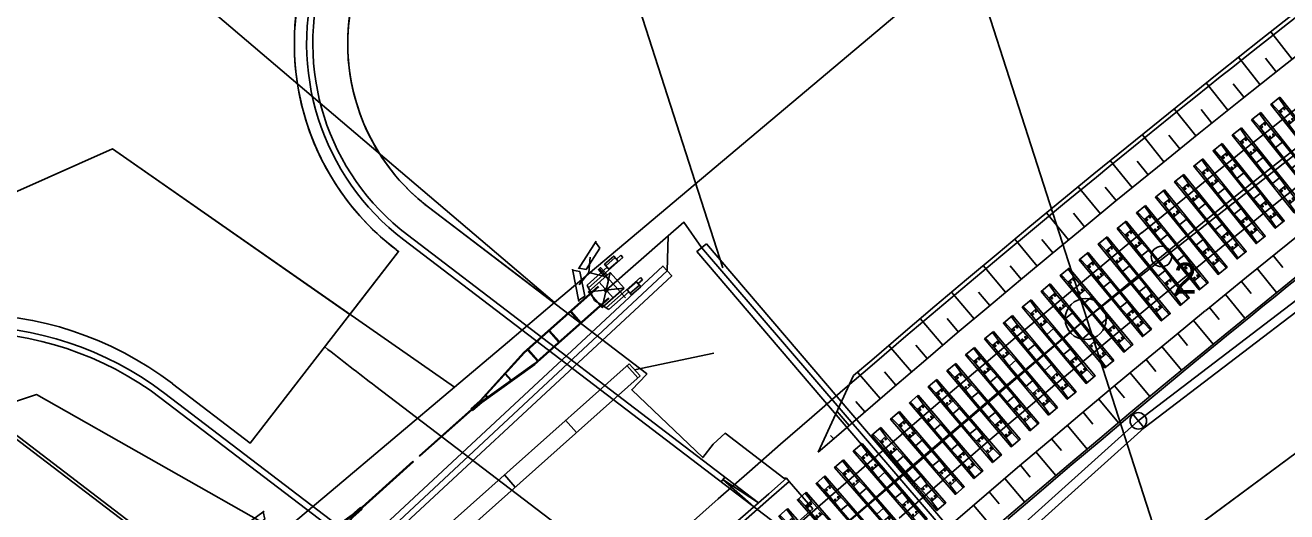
# Model space of a CAD drawing. Extents: x -758836 to -757729, y -1175316 to -1174366.
# Drawn here: x -758418.54 to -758387.81, y -1174837.29 to -1174825.45 of the extents above; entities that cross this region are included whole.
import ezdxf

# ---------------------------------------------------------------- set-up
doc = ezdxf.new("R2010")
doc.units = 0
for name, color, linetype in [('_NOR-návrh silná', 7, 'Continuous'), ('_NOR-návrh tenká', 7, 'Continuous'), ('_NOR-osa', 7, 'Continuous'), ('_NOR-pomocná', 7, 'Continuous'), ('_NOR-popis', 7, 'Continuous'), ('_NOR-pražce', 7, 'Continuous'), ('_NOR-přejezdová konstrukce', 7, 'Continuous'), ('_NOR-sanace', 7, 'Continuous'), ('_NOR-svahy', 7, 'Continuous'), ('_NOR-vytyčení', 7, 'Continuous'), ('G_Obvod stavby', 7, 'Continuous'), ('Hranice parcel', 7, 'Continuous'), ('KOS_kabely SSZT', 7, 'Continuous'), ('KOS_PZZ nové', 7, 'Continuous'), ('Vrstva 1', 7, 'Continuous')]:
    doc.layers.add(name, color=color, linetype=linetype)

# ---------------------------------------------------------------- blocks, each defined once
blk = doc.blocks.new('půdorys-SB8')
at = {"layer": '_NOR-pražce'}
for p, q in [((-1.21, 0.109), (-0.96, 0.095)), ((-0.96, 0.095), (-0.56, 0.099)), ((-0.96, 0.095), (-0.96, -0.095)), ((-0.56, 0.099), (-0.32, 0.109)), ((-0.56, 0.099), (-0.56, -0.1)), ((-0.32, 0.109), (0.32, 0.109)), ((-0.32, 0.109), (-0.32, -0.11)), ((0.56, 0.099), (0.32, 0.109)), ((0.32, -0.11), (0.32, 0.109)), ((0.96, 0.095), (0.56, 0.099)), ((0.56, 0.099), (0.56, -0.1)), ((1.21, 0.109), (0.96, 0.095)), ((0.96, 0.095), (0.96, -0.095)), ((-1.21, -0.11), (-0.96, -0.095)), ((-0.96, -0.095), (-0.56, -0.1)), ((-0.56, -0.1), (-0.32, -0.11)), ((-0.32, -0.11), (0.32, -0.11)), ((0.56, -0.1), (0.32, -0.11)), ((0.96, -0.095), (0.56, -0.1)), ((1.21, -0.11), (0.96, -0.095))]:
    blk.add_line(p, q, dxfattribs=at)
blk.add_lwpolyline([(-1.21, 0.142), (1.21, 0.142), (1.21, -0.142), (-1.21, -0.142)], close=True, dxfattribs=at)
for centre in [(-0.916, 0.048), (-0.604, 0.048), (0.604, 0.048), (0.916, 0.048), (-0.916, -0.048), (-0.604, -0.048), (0.604, -0.048), (0.916, -0.048)]:
    blk.add_circle(centre, 0.015, dxfattribs=at)
blk = doc.blocks.new('A$C45C32C5D')
for p, q in [((0.338, 0.725), (0, 0)), ((0.328, 0.702), (0.449, 0.568)), ((0.011, 0.023), (0.192, 0.016))]:
    blk.add_line(p, q)
blk.add_lwpolyline([(0.449, 0.568), (0.192, 0.016)])
blk = doc.blocks.new('A$C45E25FDC')
for p, q in [((0.029, 0.671), (0.224, 0.671)), ((0.341, 0.159), (0.341, 0.557)), ((0.341, 0.159), (0, 0))]:
    blk.add_line(p, q)
blk.add_arc((0.227, 0.557), 0.115, 0.0129, 91.4438)
blk = doc.blocks.new('Závora 8m')
for p, q in [((0.083, -0.373), (-0.058, -0.373)), ((-0.058, -0.448), (-0.058, -0.373)), ((1.054, -0.448), (-0.058, -0.448)), ((1.032, -0.373), (0.382, -0.373)), ((0.413, -1.026), (1.122, -0.517)), ((0.413, -0.517), (1.122, -1.026)), ((0.542, -0.323), (0.542, -1.27)), ((0.767, -0.517), (0.767, -1.026)), ((0.851, -0.571), (5.271, -0.571)), ((0.851, -0.591), (5.271, -0.591)), ((1.149, -0.771), (1.032, -0.373)), ((1.751, -0.591), (1.751, -0.951)), ((1.771, -0.591), (1.771, -0.951)), ((2.451, -0.591), (2.451, -0.951)), ((2.471, -0.591), (2.471, -0.951)), ((3.151, -0.591), (3.151, -0.951)), ((3.171, -0.591), (3.171, -0.951)), ((3.851, -0.591), (3.851, -0.951)), ((3.871, -0.591), (3.871, -0.951)), ((4.551, -0.591), (4.551, -0.951)), ((4.571, -0.591), (4.571, -0.951)), ((5.251, -0.591), (5.251, -0.951)), ((5.271, -0.571), (6.851, -0.741)), ((5.271, -0.591), (5.271, -0.951)), ((5.271, -0.591), (6.851, -0.761)), ((1.149, -0.771), (1.032, -1.17)), ((6.851, -0.781), (5.271, -0.951)), ((5.271, -0.971), (6.851, -0.801)), ((5.951, -0.665), (5.951, -0.878)), ((5.971, -0.667), (5.971, -0.876)), ((6.651, -0.74), (6.651, -0.803)), ((6.671, -0.742), (6.671, -0.801)), ((6.851, -0.741), (7.151, -0.741)), ((8.851, -0.761), (6.851, -0.761)), ((6.851, -0.761), (6.851, -0.781)), ((6.851, -0.761), (7.151, -0.761)), ((8.851, -0.781), (6.851, -0.781)), ((6.851, -0.781), (7.151, -0.781)), ((6.851, -0.801), (7.151, -0.801)), ((7.151, -0.741), (7.151, -0.761)), ((7.151, -0.801), (7.151, -0.781)), ((8.851, -0.761), (8.851, -0.781)), ((1.054, -1.095), (-0.058, -1.095)), ((-0.058, -1.095), (-0.058, -1.17)), ((0.083, -1.17), (-0.058, -1.17)), ((1.032, -1.17), (0.382, -1.17)), ((0.851, -0.951), (5.271, -0.951)), ((0.851, -0.971), (5.271, -0.971))]:
    blk.add_line(p, q)
for points in [[(0.382, -0.434), (0.083, -0.434), (0.083, -0.274), (0.382, -0.274)], [(0.382, -0.324), (0.083, -0.324), (0.083, -0.274), (0.382, -0.274)], [(0.413, -0.517), (1.122, -0.517), (1.122, -1.026), (0.413, -1.026)], [(0.382, -1.109), (0.083, -1.109), (0.083, -1.269), (0.382, -1.269)], [(0.382, -1.219), (0.083, -1.219), (0.083, -1.269), (0.382, -1.269)]]:
    blk.add_lwpolyline(points, close=True)
blk.add_lwpolyline([(0.507, -1.048), (0.507, -1.27), (0.578, -1.27), (0.578, -1.048)])
for start, end in [(130.1075, 310.1075), (310.1075, 130.1075)]:
    blk.add_arc((0.767, -0.771), 0.0422, start, end)
blk = doc.blocks.new('Závora 6m')
for p, q in [((0.083, -0.373), (-0.058, -0.373)), ((-0.058, -0.448), (-0.058, -0.373)), ((1.054, -0.448), (-0.058, -0.448)), ((1.032, -0.373), (0.382, -0.373)), ((0.413, -1.026), (1.122, -0.517)), ((0.413, -0.517), (1.122, -1.026)), ((0.542, -0.323), (0.542, -1.27)), ((0.767, -0.517), (0.767, -1.026)), ((0.851, -0.571), (3.271, -0.571)), ((0.851, -0.591), (3.271, -0.591)), ((1.149, -0.771), (1.032, -0.373)), ((1.751, -0.591), (1.751, -0.951)), ((1.771, -0.591), (1.771, -0.951)), ((2.451, -0.591), (2.451, -0.951)), ((2.471, -0.591), (2.471, -0.951)), ((3.151, -0.591), (3.151, -0.951)), ((3.171, -0.591), (3.171, -0.951)), ((3.271, -0.571), (4.851, -0.741)), ((3.271, -0.591), (4.851, -0.761)), ((1.149, -0.771), (1.032, -1.17)), ((4.851, -0.781), (3.271, -0.951)), ((3.271, -0.971), (4.851, -0.801)), ((3.951, -0.665), (3.951, -0.878)), ((3.971, -0.667), (3.971, -0.876)), ((4.651, -0.74), (4.651, -0.803)), ((4.671, -0.742), (4.671, -0.801)), ((4.851, -0.741), (5.151, -0.741)), ((6.851, -0.761), (4.851, -0.761)), ((4.851, -0.761), (4.851, -0.781)), ((4.851, -0.761), (5.151, -0.761)), ((6.851, -0.781), (4.851, -0.781)), ((4.851, -0.781), (5.151, -0.781)), ((4.851, -0.801), (5.151, -0.801)), ((5.151, -0.741), (5.151, -0.761)), ((5.151, -0.801), (5.151, -0.781)), ((6.851, -0.761), (6.851, -0.781)), ((1.054, -1.095), (-0.058, -1.095)), ((-0.058, -1.095), (-0.058, -1.17)), ((0.083, -1.17), (-0.058, -1.17)), ((1.032, -1.17), (0.382, -1.17)), ((0.851, -0.951), (3.271, -0.951)), ((0.851, -0.971), (3.271, -0.971))]:
    blk.add_line(p, q)
for points in [[(0.382, -0.434), (0.083, -0.434), (0.083, -0.274), (0.382, -0.274)], [(0.382, -0.324), (0.083, -0.324), (0.083, -0.274), (0.382, -0.274)], [(0.413, -0.517), (1.122, -0.517), (1.122, -1.026), (0.413, -1.026)], [(0.382, -1.109), (0.083, -1.109), (0.083, -1.269), (0.382, -1.269)], [(0.382, -1.219), (0.083, -1.219), (0.083, -1.269), (0.382, -1.269)]]:
    blk.add_lwpolyline(points, close=True)
blk.add_lwpolyline([(0.507, -1.048), (0.507, -1.27), (0.578, -1.27), (0.578, -1.048)])
for start, end in [(130.1075, 310.1075), (310.1075, 130.1075)]:
    blk.add_arc((0.767, -0.771), 0.0422, start, end)
blk = doc.blocks.new('POINT_DISPLAY')
blk.add_line((0, 0), (0, 0))

msp = doc.modelspace()

# ---------------------------------------------------------------- linework, layer by layer
at = {"layer": '_NOR-návrh silná'}
msp.add_line((-758421.766, -1174833.13), (-758401.3, -1174848.727), dxfattribs=at)
for points in [[(-758409.317, -1174830.673), (-758395.764, -1174841.002)], [(-758399.411, -1174846.395), (-758415.134, -1174834.412)]]:
    msp.add_lwpolyline(points, dxfattribs=at)
for centre, radius, start, end in [((-758405.68, -1174825.901), 6, 162.5481, 232.6885), ((-758419.983, -1174840.775), 8, 52.6885, 127.8448)]:
    msp.add_arc(centre, radius, start, end, dxfattribs=at)
at = {"layer": '_NOR-návrh tenká'}
for p, q in [((-758391.422, -1174835.079), (-758371.266, -1174819.688)), ((-758391.278, -1174835.252), (-758371.14, -1174819.874)), ((-758403.693, -1174833.836), (-758401.766, -1174833.434)), ((-758410.412, -1174839.554), (-758403.826, -1174833.687)), ((-758403.878, -1174833.734), (-758403.612, -1174834.032)), ((-758403.826, -1174833.687), (-758403.56, -1174833.986)), ((-758410.146, -1174839.852), (-758403.56, -1174833.986)), ((-758410.366, -1174852.055), (-758391.422, -1174835.079)), ((-758405.372, -1174835.064), (-758405.106, -1174835.363)), ((-758391.567, -1174834.907), (-758391.278, -1174835.252)), ((-758410.212, -1174852.218), (-758391.278, -1174835.252)), ((-758406.865, -1174836.394), (-758406.599, -1174836.693)), ((-758401.584, -1174836.566), (-758401.493, -1174836.447)), ((-758400.789, -1174837.173), (-758401.539, -1174836.507)), ((-758401.539, -1174836.507), (-758400.673, -1174837.072))]:
    msp.add_line(p, q, dxfattribs=at)
for points in [[(-758399.22, -1174835.845), (-758398.357, -1174833.975), (-758397.917, -1174833.598), (-758397.15, -1174832.943), (-758396.382, -1174832.291), (-758395.611, -1174831.641), (-758394.838, -1174830.994), (-758394.062, -1174830.349), (-758393.285, -1174829.706), (-758392.507, -1174829.068)], [(-758408.71, -1174829.878), (-758403.402, -1174833.923), (-758403.405, -1174833.947), (-758403.761, -1174834.321), (-758402.034, -1174835.972), (-758401.778, -1174835.646), (-758401.489, -1174835.381), (-758400.057, -1174836.473), (-758399.995, -1174836.478)], [(-758399.22, -1174835.845), (-758398.887, -1174835.555), (-758398.127, -1174834.898), (-758397.364, -1174834.243), (-758396.599, -1174833.591), (-758395.833, -1174832.94), (-758395.064, -1174832.292), (-758394.293, -1174831.646), (-758393.52, -1174831.003), (-758392.745, -1174830.362), (-758391.968, -1174829.725)], [(-758409.226, -1174830.554), (-758400.674, -1174837.072)], [(-758399.743, -1174837.628), (-758398.989, -1174836.968), (-758398.232, -1174836.311), (-758397.474, -1174835.656), (-758396.714, -1174835.003), (-758395.951, -1174834.352), (-758395.187, -1174833.704), (-758394.421, -1174833.058), (-758393.652, -1174832.414), (-758392.882, -1174831.773), (-758392.109, -1174831.134), (-758391.334, -1174830.498)], [(-758409.498, -1174830.912), (-758409.442, -1174830.955), (-758413.055, -1174835.619), (-758414.952, -1174834.174)], [(-758397.25, -1174837.445), (-758396.495, -1174836.792), (-758395.738, -1174836.142), (-758394.979, -1174835.494), (-758394.218, -1174834.849), (-758393.456, -1174834.206), (-758392.691, -1174833.566), (-758391.924, -1174832.927), (-758391.155, -1174832.292), (-758390.384, -1174831.659)], [(-758396.95, -1174838.443), (-758396.628, -1174838.163), (-758395.875, -1174837.512), (-758395.12, -1174836.864), (-758394.364, -1174836.218), (-758393.605, -1174835.574), (-758392.844, -1174834.933), (-758392.082, -1174834.295), (-758391.318, -1174833.659), (-758390.551, -1174833.025), (-758389.782, -1174832.394)], [(-758396.95, -1174838.443), (-758395.018, -1174837.764), (-758394.632, -1174837.434), (-758393.877, -1174836.789), (-758393.121, -1174836.147), (-758392.362, -1174835.508), (-758391.601, -1174834.871), (-758390.839, -1174834.236), (-758390.074, -1174833.604), (-758389.306, -1174832.974)], [(-758408.073, -1174843.666), (-758421.866, -1174833.154)], [(-758409.998, -1174834.24), (-758401.824, -1174840.47)], [(-758405.836, -1174841.687), (-758415.225, -1174834.532)]]:
    msp.add_lwpolyline(points, dxfattribs=at)
msp.add_circle((-758391.422, -1174835.079), 0.2, dxfattribs=at)
for centre, radius, start, end in [((-758205.34, -1175057.864), 295.6, 97.09776, 129.28488), ((-758205.34, -1175057.864), 294.75, 97.0979, 129.28474), ((-758205.34, -1175057.864), 291.3, 97.09848, 129.28417), ((-758205.34, -1175057.864), 290.55, 97.09861, 129.28404), ((-758205.34, -1175057.864), 293.75, 120.96729, 129.28457), ((-758205.34, -1175057.864), 292.25, 120.96729, 129.28432), ((-758405.68, -1174825.901), 6.3, 162.5481, 232.6885), ((-758405.68, -1174825.901), 5.85, 162.5481, 232.6885), ((-758405.68, -1174825.901), 5, 162.5481, 232.6885), ((-758419.983, -1174840.775), 8.3, 52.6885, 127.8448), ((-758419.983, -1174840.775), 7.85, 52.6885, 127.8448), ((-758349.383, -1174754.705), 100, 231.78754, 232.68848)]:
    msp.add_arc(centre, radius, start, end, dxfattribs=at)
at = {"layer": '_NOR-osa'}
msp.add_lwpolyline([(-758398.496, -1174837.534), (-758397.741, -1174836.878), (-758396.984, -1174836.224), (-758396.226, -1174835.573), (-758395.465, -1174834.923), (-758394.703, -1174834.276), (-758393.938, -1174833.632), (-758393.171, -1174832.99), (-758392.403, -1174832.35), (-758391.632, -1174831.713), (-758390.859, -1174831.079)], dxfattribs=at)
msp.add_circle((-758390.859, -1174831.079), 0.25, dxfattribs=at)
msp.add_arc((-758205.34, -1175057.864), 293, 97.09819, 129.28445, dxfattribs=at)
at = {"layer": '_NOR-pomocná'}
for points in [[(-758417.595, -1174755.224), (-758317.652, -1174723.031), (-758272.123, -1174864.38), (-758372.066, -1174896.572)], [(-758517.538, -1174787.416), (-758417.595, -1174755.224), (-758372.066, -1174896.572), (-758472.009, -1174928.764)]]:
    msp.add_lwpolyline(points, close=True, dxfattribs=at)
at = {"layer": '_NOR-popis'}
msp.add_lwpolyline([(-758411.267, -1174770.178), (-758420.309, -1174773.091), (-758401.541, -1174831.358)], dxfattribs=at)
msp.add_circle((-758392.703, -1174832.599), 0.5, dxfattribs=at)
at = {"layer": '_NOR-přejezdová konstrukce'}
msp.add_line((-758399.349, -1174837.217), (-758399.93, -1174836.553), dxfattribs=at)
for points in [[(-758406.208, -1174842.161), (-758406.276, -1174842.087), (-758405.669, -1174841.535), (-758404.925, -1174840.86), (-758404.179, -1174840.188), (-758403.432, -1174839.517), (-758402.682, -1174838.848), (-758401.931, -1174838.18), (-758401.178, -1174837.515), (-758400.423, -1174836.852), (-758399.995, -1174836.478), (-758399.93, -1174836.553)], [(-758406.208, -1174842.161), (-758405.602, -1174841.609), (-758404.858, -1174840.934), (-758404.112, -1174840.262), (-758403.365, -1174839.591), (-758402.616, -1174838.922), (-758401.865, -1174838.255), (-758401.112, -1174837.59), (-758400.358, -1174836.927), (-758399.93, -1174836.553)], [(-758405.615, -1174842.813), (-758405.009, -1174842.262), (-758404.266, -1174841.589), (-758403.522, -1174840.918), (-758402.777, -1174840.248), (-758402.029, -1174839.581), (-758401.28, -1174838.915), (-758400.529, -1174838.252), (-758399.776, -1174837.59), (-758399.349, -1174837.217)]]:
    msp.add_lwpolyline(points, dxfattribs=at)
at = {"layer": '_NOR-sanace'}
for points in [[(-758402.407, -1174837.643), (-758401.653, -1174836.976), (-758400.897, -1174836.312), (-758400.138, -1174835.649), (-758399.378, -1174834.988), (-758398.616, -1174834.33), (-758397.852, -1174833.673), (-758397.085, -1174833.019), (-758396.317, -1174832.367), (-758395.546, -1174831.718), (-758394.774, -1174831.071), (-758393.999, -1174830.426), (-758393.221, -1174829.783), (-758392.444, -1174829.145)], [(-758394.6, -1174837.472), (-758393.845, -1174836.827), (-758393.088, -1174836.185), (-758392.33, -1174835.546), (-758391.569, -1174834.909), (-758390.807, -1174834.275), (-758390.043, -1174833.643), (-758389.274, -1174833.012)]]:
    msp.add_lwpolyline(points, dxfattribs=at)
for radius, end in [(295.5, 129.28486), (290.5, 129.28403)]:
    msp.add_arc((-758205.34, -1175057.864), radius, 124.47202, end, dxfattribs=at)
at = {"layer": '_NOR-svahy'}
for points in [[(-758387.671, -1174826.276), (-758388.197, -1174825.608)], [(-758388.455, -1174826.896), (-758388.984, -1174826.23)], [(-758388.063, -1174826.586), (-758388.327, -1174826.252)], [(-758389.238, -1174827.519), (-758389.768, -1174826.854)], [(-758388.847, -1174827.207), (-758389.112, -1174826.874)], [(-758390.018, -1174828.144), (-758390.551, -1174827.481)], [(-758389.628, -1174827.831), (-758389.894, -1174827.499)], [(-758390.797, -1174828.772), (-758391.332, -1174828.111)], [(-758390.408, -1174828.457), (-758390.675, -1174828.127)], [(-758391.573, -1174829.402), (-758392.11, -1174828.743)], [(-758391.185, -1174829.087), (-758391.453, -1174828.757)], [(-758392.347, -1174830.036), (-758392.886, -1174829.379)], [(-758391.96, -1174829.718), (-758392.229, -1174829.389)], [(-758393.119, -1174830.671), (-758393.66, -1174830.016)], [(-758392.733, -1174830.353), (-758393.003, -1174830.024)], [(-758393.888, -1174831.31), (-758394.432, -1174830.656)], [(-758393.504, -1174830.99), (-758393.775, -1174830.662)], [(-758388.136, -1174831.057), (-758387.901, -1174831.349)], [(-758394.656, -1174831.95), (-758395.202, -1174831.299)], [(-758394.273, -1174831.629), (-758394.545, -1174831.303)], [(-758388.525, -1174831.371), (-758388.053, -1174831.954)], [(-758388.913, -1174831.686), (-758388.677, -1174831.977)], [(-758395.422, -1174832.594), (-758395.97, -1174831.944)], [(-758395.039, -1174832.272), (-758395.312, -1174831.946)], [(-758389.301, -1174832.002), (-758388.828, -1174832.583)], [(-758389.689, -1174832.318), (-758389.451, -1174832.608)], [(-758396.185, -1174833.239), (-758396.735, -1174832.591)], [(-758395.804, -1174832.916), (-758396.078, -1174832.591)], [(-758390.075, -1174832.635), (-758389.599, -1174833.214)], [(-758390.462, -1174832.952), (-758390.224, -1174833.242)], [(-758396.947, -1174833.887), (-758397.499, -1174833.241)], [(-758396.567, -1174833.563), (-758396.842, -1174833.239)], [(-758390.847, -1174833.27), (-758390.37, -1174833.848)], [(-758391.233, -1174833.589), (-758390.994, -1174833.878)], [(-758397.707, -1174834.538), (-758398.261, -1174833.893)], [(-758397.327, -1174834.212), (-758397.603, -1174833.889)], [(-758391.617, -1174833.908), (-758391.138, -1174834.485)], [(-758392.002, -1174834.228), (-758391.762, -1174834.516)], [(-758392.385, -1174834.549), (-758391.904, -1174835.124)], [(-758398.465, -1174835.19), (-758398.76, -1174834.848)], [(-758398.086, -1174834.863), (-758398.307, -1174834.606)], [(-758392.769, -1174834.87), (-758392.528, -1174835.157)], [(-758393.151, -1174835.192), (-758392.668, -1174835.765)], [(-758398.843, -1174835.517), (-758398.917, -1174835.432)], [(-758393.533, -1174835.514), (-758393.292, -1174835.801)], [(-758399.22, -1174835.845), (-758399.22, -1174835.845)], [(-758393.915, -1174835.837), (-758393.43, -1174836.409)], [(-758394.296, -1174836.161), (-758394.054, -1174836.447)], [(-758394.677, -1174836.485), (-758394.19, -1174837.056)], [(-758395.057, -1174836.81), (-758394.813, -1174837.095)], [(-758395.436, -1174837.135), (-758394.948, -1174837.704)]]:
    msp.add_lwpolyline(points, dxfattribs=at)
at = {"layer": 'G_Obvod stavby'}
for p, q in [((-758405.651, -1174832.209), (-758408.71, -1174829.878)), ((-758409.442, -1174830.955), (-758410.628, -1174832.486)), ((-758409.498, -1174830.912), (-758409.442, -1174830.955)), ((-758405.64, -1174832.2), (-758405.651, -1174832.209))]:
    msp.add_line(p, q, dxfattribs=at)
for points in [[(-758392.72, -1174840.756), (-758391.23, -1174838.56), (-758368.37, -1174821.64), (-758340.31, -1174807.33), (-758320.27, -1174796.89), (-758301, -1174790.21), (-758267.96, -1174782.93), (-758224.96, -1174775.27), (-758184.87, -1174772.83), (-758142.71, -1174770.26), (-758089.84, -1174768.68), (-758106.02, -1174731.44), (-758149.09, -1174725.67), (-758199.62, -1174726.6), (-758225.76, -1174732.36), (-758252.17, -1174738.18), (-758254.97, -1174739.34), (-758266.58, -1174744.16), (-758279.45, -1174749.49), (-758302.42, -1174759.02), (-758331.68, -1174770.24), (-758367.17, -1174799.81), (-758405.64, -1174832.2)], [(-758410.628, -1174832.486), (-758416.41, -1174828.46), (-758422.01, -1174830.95), (-758425.34, -1174833.98), (-758425.144, -1174834.274)]]:
    msp.add_lwpolyline(points, dxfattribs=at)
for radius, start, end in [(6.3, 162.5481, 188.8894), (5, 162.5481, 212.3104), (6.3, 188.8894, 232.6885), (5, 212.3104, 232.6885)]:
    msp.add_arc((-758405.68, -1174825.901), radius, start, end, dxfattribs=at)
at = {"layer": 'Hranice parcel'}
for p, q in [((-758445.41, -1174798.39), (-758405.64, -1174832.2)), ((-758405.64, -1174832.2), (-758367.17, -1174799.81))]:
    msp.add_line(p, q, dxfattribs=at)
for points in [[(-758340.31, -1174807.33), (-758368.37, -1174821.64), (-758391.23, -1174838.56)], [(-758425.34, -1174833.98), (-758422.01, -1174830.95), (-758416.41, -1174828.46), (-758408.08, -1174834.26)], [(-758405.64, -1174832.2), (-758406.79, -1174833.17), (-758408.08, -1174834.26)], [(-758408.08, -1174834.26), (-758411.08, -1174836.79), (-758412.3, -1174837.81), (-758418.26, -1174834.44), (-758423.81, -1174836.28)]]:
    msp.add_lwpolyline(points, dxfattribs=at)
at = {"layer": 'KOS_kabely SSZT'}
for points in [[(-758393.377, -1174840.127), (-758394.523, -1174839.636), (-758402.059, -1174830.861), (-758402.489, -1174830.243), (-758402.873, -1174830.574), (-758402.896, -1174831.429), (-758411.837, -1174839.758), (-758412.685, -1174838.202), (-758411.837, -1174839.758), (-758414.56, -1174842.041), (-758415.093, -1174841.478), (-758414.56, -1174842.041), (-758421.625, -1174846.632), (-758424.748, -1174843.672)], [(-758402.873, -1174830.574), (-758404.383, -1174831.895)], [(-758401.943, -1174830.766), (-758402.175, -1174830.957), (-758395.093, -1174839.249), (-758394.861, -1174839.058), (-758401.943, -1174830.766)]]:
    msp.add_lwpolyline(points, dxfattribs=at)
msp.add_lwpolyline([(-758411.517, -1174839.221), (-758403.003, -1174831.313), (-758402.788, -1174831.545), (-758411.302, -1174839.452)], close=True, dxfattribs=at)
at = {"layer": 'KOS_PZZ nové'}
msp.add_line((-758404.807, -1174831.471), (-758404.774, -1174831.096), dxfattribs=at)
at = {"layer": 'Vrstva 1'}
msp.add_lwpolyline([(-758443.817, -1174881.252), (-758441.673, -1174879.1), (-758423.412, -1174860.854), (-758412.446, -1174850.23), (-758405.322, -1174843.614), (-758399.028, -1174837.996), (-758392.64, -1174832.554), (-758380.106, -1174822.693), (-758371.773, -1174816.721), (-758363.37, -1174811.125), (-758354.46, -1174805.649), (-758345.526, -1174800.592), (-758336.614, -1174795.909), (-758327.338, -1174791.462), (-758317.813, -1174787.314), (-758307.666, -1174783.315), (-758298.059, -1174779.921), (-758285.017, -1174775.914), (-758275.047, -1174773.289)], dxfattribs=at)

# ---------------------------------------------------------------- block references
at = {"layer": '_NOR-pražce'}
for p, rotation in [((-758387.331, -1174828.238), -51.60136444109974), ((-758387.799, -1174828.61), -51.48433478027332), ((-758388.267, -1174828.983), -51.36730508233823), ((-758388.734, -1174829.357), -51.25027544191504), ((-758389.201, -1174829.732), -51.133245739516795), ((-758389.666, -1174830.108), -51.0162160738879), ((-758390.131, -1174830.485), -50.899186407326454), ((-758390.595, -1174830.863), -50.78215672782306), ((-758391.058, -1174831.242), -50.618338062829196), ((-758391.522, -1174831.622), -50.61833808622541), ((-758391.982, -1174832.003), -50.426160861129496), ((-758392.443, -1174832.384), -50.237355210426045), ((-758392.904, -1174832.767), -50.23735517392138), ((-758393.363, -1174833.15), -50.051921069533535), ((-758393.823, -1174833.535), -50.051921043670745), ((-758394.28, -1174833.92), -49.869858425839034), ((-758394.737, -1174834.306), -49.69116733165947), ((-758395.195, -1174834.694), -49.691167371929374), ((-758395.65, -1174835.081), -49.51584778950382), ((-758396.106, -1174835.47), -49.51584780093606), ((-758396.56, -1174835.86), -49.34389977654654), ((-758397.013, -1174836.249), -49.17532329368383), ((-758397.468, -1174836.641), -49.17532330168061), ((-758397.919, -1174837.033), -49.01011836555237), ((-758398.372, -1174837.426), -49.01011829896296), ((-758398.823, -1174837.819), -48.848284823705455), ((-758399.273, -1174838.213), -48.68982295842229)]:
    msp.add_blockref('půdorys-SB8', p, dxfattribs=dict(at, rotation=rotation))
at = {"layer": '_NOR-vytyčení'}
msp.add_blockref('POINT_DISPLAY', (-758390.859, -1174831.079), dxfattribs=at)
at = {"layer": 'KOS_PZZ nové'}
for name, p, yscale, rotation in [('A$C45C32C5D', (-758404.63, -1174830.708), -1, -57.520567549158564), ('A$C45C32C5D', (-758405.206, -1174831.385), -1.0000000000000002, -13.953639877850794), ('A$C45E25FDC', (-758405.042, -1174831.765), -1, 76.38095475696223), ('A$C45C32C5D', (-758412.719, -1174837.28), -0.9999999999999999, -78.34965295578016)]:
    msp.add_blockref(name, p, dxfattribs=dict(at, yscale=yscale, rotation=rotation))
for name, p, rotation in [('Závora 6m', (-758403.297, -1174831.963), -138.41254315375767), ('Závora 8m', (-758416.18, -1174841.418), 42.00076019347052)]:
    msp.add_blockref(name, p, dxfattribs=dict(at, rotation=rotation))

# ---------------------------------------------------------------- texts
at = {"layer": '_NOR-vytyčení'}
msp.add_text('2', height=0.75, rotation=360, dxfattribs=at).set_placement((-758390.559, -1174831.979))

doc.saveas('drawing.dxf')
